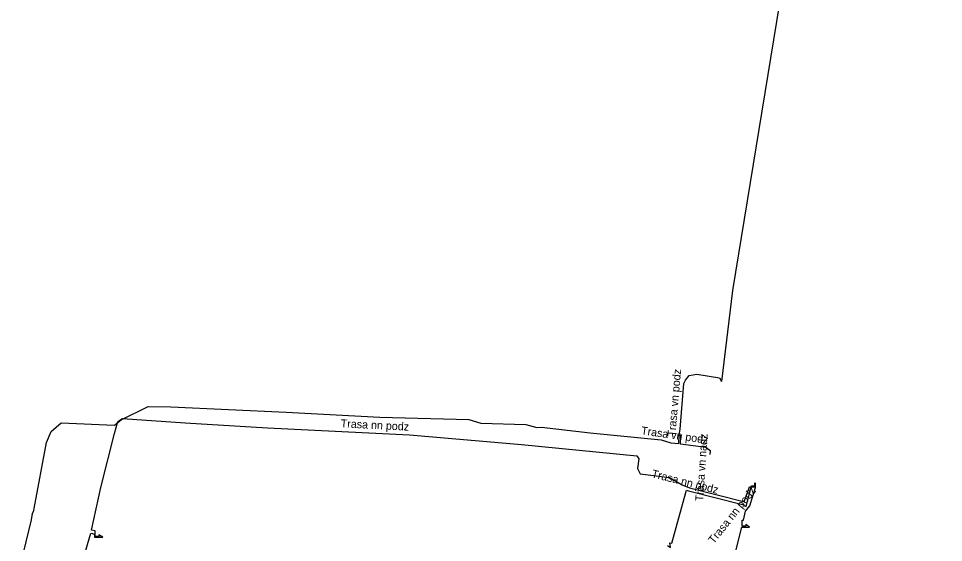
# Model space of a CAD drawing. Extents: x -742082 to -717476, y -1040737 to -1024597.
# Drawn here: x -735539.5 to -735423.9, y -1031989.3 to -1031923.8 of the extents above; entities that cross this region are included whole.
import ezdxf

# ---------------------------------------------------------------- set-up
doc = ezdxf.new("R2010")
doc.units = 0
for name, color, linetype in [('Level 15', 7, 'Continuous'), ('Level 20', 7, 'Continuous'), ('Level 24', 7, 'Continuous'), ('Level 25', 7, 'Continuous')]:
    doc.layers.add(name, color=color, linetype=linetype)

msp = doc.modelspace()

# ---------------------------------------------------------------- linework, layer by layer
at = {"layer": 'Level 15'}
for points in [[(-735529.45, -1031988.3), (-735529.45, -1031988.51), (-735529.9, -1031988.51), (-735529.9, -1031987.82), (-735530.36, -1031987.71), (-735529.22, -1031982.4), (-735527.52, -1031975.63), (-735527.08, -1031974.14), (-735526.5, -1031973.79), (-735518.66, -1031974.3), (-735508.39, -1031974.92), (-735490.66, -1031975.81), (-735476.63, -1031977.04), (-735462.23, -1031978.44), (-735461.97, -1031978.82), (-735462.16, -1031980.03), (-735461.82, -1031980.67), (-735458.17, -1031981.15), (-735456.58, -1031982.08), (-735455.66, -1031982.42), (-735448.91, -1031984.13), (-735448.82, -1031984.18), (-735448.16, -1031982.29), (-735447.51, -1031982.29), (-735447.51, -1031981.79)], [(-735458.39, -1031989.66), (-735458.02, -1031989.87), (-735458.1, -1031989.32), (-735457.86, -1031989.36), (-735456.12, -1031983.02), (-735456.02, -1031982.71), (-735455.78, -1031982.8), (-735449.05, -1031984.5), (-735448.56, -1031984.77), (-735447.91, -1031982.19), (-735447.46, -1031982.19), (-735447.46, -1031981.79)], [(-735448.61, -1031987.02), (-735448.61, -1031987.23), (-735449.06, -1031987.23), (-735449.06, -1031986.47), (-735448.91, -1031986.47), (-735448.66, -1031985.34), (-735448.12, -1031984.67), (-735447.43, -1031982.41), (-735447.43, -1031981.79)], [(-735451.92, -1032001.95), (-735451.44, -1032002.26), (-735451.52, -1032001.41), (-735452.59, -1032001.38), (-735452.5, -1032000.68), (-735449.11, -1031987.33), (-735448.14, -1031987.33), (-735448.61, -1031987.02)], [(-735531.36, -1031996.63), (-735531.36, -1031996.84), (-735531.81, -1031996.84), (-735531.81, -1031996.13), (-735532.13, -1031996.05), (-735531.37, -1031991.21), (-735530.46, -1031988.1), (-735530, -1031988.21), (-735530, -1031988.61), (-735528.98, -1031988.61), (-735529.45, -1031988.3)]]:
    msp.add_lwpolyline(points, dxfattribs=at)
at = {"layer": 'Level 24'}
for points in [[(-735423.92, -1031780.81), (-735433.68, -1031844.94), (-735441.14, -1031901.71), (-735450.27, -1031957.76), (-735451.65, -1031969.15)], [(-735453.06, -1031978.26), (-735453.03, -1031977.8), (-735453.25, -1031977.67)]]:
    msp.add_lwpolyline(points, dxfattribs=at)
at = {"layer": 'Level 25'}
for points in [[(-735456.93, -1031975.84), (-735456.84, -1031975.12), (-735456.35, -1031969.38), (-735456.14, -1031968.99), (-735455.7, -1031968.39), (-735454.74, -1031968.22), (-735451.91, -1031968.71), (-735451.66, -1031969.15)], [(-735539.5, -1031993.12), (-735537.88, -1031986.43), (-735537.77, -1031985.64), (-735537.59, -1031985.28), (-735537.54, -1031985), (-735536.02, -1031976.76), (-735535.42, -1031975.38), (-735534.18, -1031974.31), (-735527.51, -1031974.6), (-735526.66, -1031973.93), (-735523.3, -1031972.26), (-735520.46, -1031972.31), (-735506.04, -1031972.97), (-735494.34, -1031973.59), (-735483.21, -1031973.9), (-735481.72, -1031974.36), (-735476.09, -1031974.53), (-735474.75, -1031974.9), (-735474.14, -1031974.86), (-735468.08, -1031975.56), (-735459.2, -1031976.42), (-735457.97, -1031976.82), (-735457, -1031976.9), (-735456.93, -1031975.84)], [(-735453.25, -1031977.67), (-735453.6, -1031977.41), (-735456.8, -1031976.96), (-735456.73, -1031975.95), (-735456.93, -1031975.84)]]:
    msp.add_lwpolyline(points, dxfattribs=at)

# ---------------------------------------------------------------- texts
at = {"layer": 'Level 20'}
for s, rotation, p in [('Trasa vn podz', 85.0475, (-735457.43, -1031976.07)), ('Trasa nn podz', 357.1363, (-735499.26, -1031974.87)), ('Trasa vn podz', 351.8938, (-735461.75, -1031975.75)), ('Trasa vn nadz', 86.2066, (-735453.95, -1031984.15)), ('Trasa nn podz', 345.7903, (-735460.47, -1031981.1)), ('Trasa nn podz', 51.2713, (-735452.63, -1031989.5))]:
    msp.add_text(s, height=1, rotation=rotation, dxfattribs=at).set_placement(p)

doc.saveas('drawing.dxf')
